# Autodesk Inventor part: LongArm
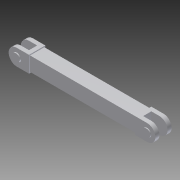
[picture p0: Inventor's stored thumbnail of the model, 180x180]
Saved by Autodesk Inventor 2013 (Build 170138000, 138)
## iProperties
Created: 2004-11
Document SubType Name: Modeling
Designer: Autodesk, Inc.
Manufacturer: Standard
Standards Organization: Custom
Description: SWING ARM, LONG ARM
Mass: 841.423 g
Surface Area: 937.387 cm^2
Volume: 841.423 cm^3
Density: 1 g/cm^3
Material: Allgemein
CAGE: 1LJX3
Dept. ID: Product Design
Description #2: ---
Finish #1: ---
Finish #2: ---
Material ID: ---
Project Number: ---
Author: Autodesk, Inc.
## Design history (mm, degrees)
sketch "Sketch1"
  geometry: L1 (0, 25.4)-(406.4, 25.4); L2 (406.4, 25.4)-(406.4, -25.4); L3 (406.4, -25.4)-(0, -25.4); L4 (0, -25.4)-(0, 25.4); 3 further points
  constraints: 8 end point, 2 midpoint, 2 parallel, 2 vertical alignment, 1 coincident, 1 horizontal, 1 perpendicular, 4 other
  dimensions: "d0" = 406.4 distance of L1.start L1.end; "d1" = 50.8 distance of L1.end L2.end
extrude "Extrusion1" new body sketch "Sketch1" stored distance "d2" = 50.8; taper "d3" = 0 deg
sketch "Sketch2"
  geometry: L1 (-25.4, 50.8)-(-25.4, 0) reference; L2 (-25.4, 50.8)-(0, 50.8) reference; L3 (0, 0)-(-25.4, 0) reference; L4 (0, 0)-(406.4, 0) reference; L5 (406.4, 50.8)-(0, 50.8) reference; L6 (-25.4, 12.7)-(25.4, 12.7); L7 (25.4, 12.7)-(25.4, 38.1); L8 (25.4, 38.1)-(-25.4, 38.1); L9 (-25.4, 38.1)-(-25.4, 12.7); 2 further points
  constraints: 8 end point, 2 midpoint, 2 parallel, 1 coincident, 1 horizontal, 1 perpendicular, 1 point on line
  dimensions: "d4" = 25.4 distance of L6.end L7.end; "d10" = 50.8 distance of L7.end L8.end
extrude "Extrusion2" cut sketch "Sketch2" stored distance "d5" = 50.8; taper "d6" = 0 deg
workplane "Work Plane1"
workplane "Work Plane2"
workplane "Work Plane3"
sketch "Sketch5"
  geometry: L1 (0, 25.4)-(406.4, 25.4) reference; L2 (406.4, -25.4)-(0, -25.4) reference; L3 (38.1, 25.4)-(38.1, -25.4); L4 (368.3, 25.4)-(368.3, -25.4); C1 r 25.4 at (0, 0); C2 r 25.4 at (406.4, 0); A1 r 25.4 centre (406.4, 0) between (406.4, -25.4) and (406.4, 25.4) reference; A2 r 25.4 centre (0, 0) between (0, 25.4) and (0, -25.4) reference
  constraints: 4 end point, 4 point on line, 2 centre point, 2 coincident, 2 concentric, 2 perpendicular
  dimensions: "d11" = 12.7 distance edge to line of C1 L3; "d13" = 12.7 distance edge to line of C2 L4 (= d11)
extrude "Extrusion4" cut sketch "Sketch5" distance "d14" = 3.175; taper "d15" = 0 deg
pattern_circular "Circular Pattern1" dims angle "d18" = 360 deg
mirror "Mirror1"
sketch "Sketch3"
  geometry: C1 r 12.7 at (0, 0); C2 r 12.7 at (406.4, 0); A1 r 25.4 centre (0, 0) between (0, 25.4) and (0, -25.4) reference; A2 r 25.4 centre (406.4, 0) between (406.4, -25.4) and (406.4, 25.4) reference
  constraints: 2 centre point, 2 coincident, 1 equal radius
  dimensions: "d7" = 25.4 diameter of C1
extrude "Extrusion3" join sketch "Sketch3" distance "d8" = 3.175; taper "d9" = 0 deg
mirror "Mirror2"
body "Solid1"
node "Projected Loop1"
